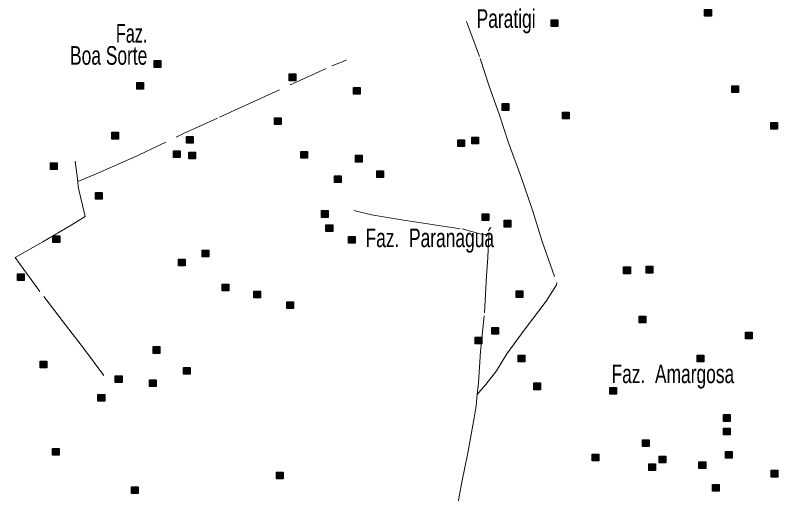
# Model space of a CAD drawing. Extents: x 445.6 to 500, y 8618.1 to 8673.4.
# Drawn here: x 450.11 to 456.69, y 8630.42 to 8634.54 of the extents above; entities that cross this region are included whole.
import ezdxf
from ezdxf.enums import TextEntityAlignment as Align

# ---------------------------------------------------------------- set-up
doc = ezdxf.new("R2010")
doc.units = 0
doc.header["$LTSCALE"] = 0.064
doc.linetypes.add('DOT_DASHED', pattern=[7.7, 5, -1.2, 0.3, -1.2])
doc.layers.add('2', color=7, linetype='Continuous', lineweight=25)
doc.layers.add('22', color=7, linetype='DOT_DASHED', lineweight=13)
doc.layers.add('61', color=7, linetype='Continuous')

msp = doc.modelspace()

# ---------------------------------------------------------------- hatches: boundary and pattern name
at = {"layer": '2'}
for points in [[(456.0553, 8634.5853), (456.1133, 8634.5853), (456.1133, 8634.5273), (456.0553, 8634.5273)], [(454.7328, 8634.4961), (454.7908, 8634.4961), (454.7908, 8634.4381), (454.7328, 8634.4381)], [(451.3121, 8634.1451), (451.3701, 8634.1451), (451.3701, 8634.0871), (451.3121, 8634.0871)], [(452.4755, 8634.0302), (452.5335, 8634.0302), (452.5335, 8633.9722), (452.4755, 8633.9722)], [(451.1624, 8633.9561), (451.2204, 8633.9561), (451.2204, 8633.8981), (451.1624, 8633.8981)], [(453.0297, 8633.9135), (453.0877, 8633.9135), (453.0877, 8633.8555), (453.0297, 8633.8555)], [(456.2893, 8633.9276), (456.3473, 8633.9276), (456.3473, 8633.8696), (456.2893, 8633.8696)], [(454.3098, 8633.7746), (454.3678, 8633.7746), (454.3678, 8633.7166), (454.3098, 8633.7166)], [(452.3481, 8633.6523), (452.4061, 8633.6523), (452.4061, 8633.5943), (452.3481, 8633.5943)], [(454.8307, 8633.7023), (454.8887, 8633.7023), (454.8887, 8633.6443), (454.8307, 8633.6443)], [(456.6261, 8633.6126), (456.6841, 8633.6126), (456.6841, 8633.5546), (456.6261, 8633.5546)], [(450.9463, 8633.5281), (451.0043, 8633.5281), (451.0043, 8633.4701), (450.9463, 8633.4701)], [(451.5889, 8633.4911), (451.6469, 8633.4911), (451.6469, 8633.4331), (451.5889, 8633.4331)], [(453.9274, 8633.4633), (453.9854, 8633.4633), (453.9854, 8633.4053), (453.9274, 8633.4053)], [(454.0493, 8633.4855), (454.1073, 8633.4855), (454.1073, 8633.4275), (454.0493, 8633.4275)], [(451.478, 8633.3688), (451.536, 8633.3688), (451.536, 8633.3108), (451.478, 8633.3108)], [(451.611, 8633.3577), (451.669, 8633.3577), (451.669, 8633.2997), (451.611, 8633.2997)], [(452.5753, 8633.3632), (452.6333, 8633.3632), (452.6333, 8633.3052), (452.5753, 8633.3052)], [(453.0463, 8633.3299), (453.1043, 8633.3299), (453.1043, 8633.2719), (453.0463, 8633.2719)], [(450.4171, 8633.2646), (450.4751, 8633.2646), (450.4751, 8633.2066), (450.4171, 8633.2066)], [(453.2292, 8633.1965), (453.2872, 8633.1965), (453.2872, 8633.1385), (453.2292, 8633.1385)], [(452.8642, 8633.1535), (452.9222, 8633.1535), (452.9222, 8633.0955), (452.8642, 8633.0955)], [(450.805, 8633.009), (450.863, 8633.009), (450.863, 8632.951), (450.805, 8632.951)], [(452.7533, 8632.8534), (452.8113, 8632.8534), (452.8113, 8632.7954), (452.7533, 8632.7954)], [(454.1387, 8632.8256), (454.1967, 8632.8256), (454.1967, 8632.7676), (454.1387, 8632.7676)], [(452.7921, 8632.7311), (452.8501, 8632.7311), (452.8501, 8632.6731), (452.7921, 8632.6731)], [(454.3272, 8632.77), (454.3852, 8632.77), (454.3852, 8632.712), (454.3272, 8632.712)], [(450.4393, 8632.6366), (450.4973, 8632.6366), (450.4973, 8632.5786), (450.4393, 8632.5786)], [(452.9861, 8632.631), (453.0441, 8632.631), (453.0441, 8632.573), (452.9861, 8632.573)], [(451.7249, 8632.5143), (451.7829, 8632.5143), (451.7829, 8632.4563), (451.7249, 8632.4563)], [(451.5199, 8632.4365), (451.5779, 8632.4365), (451.5779, 8632.3785), (451.5199, 8632.3785)], [(455.3572, 8632.3683), (455.4152, 8632.3683), (455.4152, 8632.3103), (455.3572, 8632.3103)], [(455.5511, 8632.3739), (455.6091, 8632.3739), (455.6091, 8632.3159), (455.5511, 8632.3159)], [(450.1345, 8632.3086), (450.1925, 8632.3086), (450.1925, 8632.2506), (450.1345, 8632.2506)], [(451.8967, 8632.2197), (451.9547, 8632.2197), (451.9547, 8632.1617), (451.8967, 8632.1617)], [(452.169, 8632.1594), (452.227, 8632.1594), (452.227, 8632.1014), (452.169, 8632.1014)], [(454.4317, 8632.1627), (454.4897, 8632.1627), (454.4897, 8632.1047), (454.4317, 8632.1047)], [(452.454, 8632.0686), (452.512, 8632.0686), (452.512, 8632.0106), (452.454, 8632.0106)], [(455.4902, 8631.9459), (455.5482, 8631.9459), (455.5482, 8631.8879), (455.4902, 8631.8879)], [(454.2219, 8631.8473), (454.2799, 8631.8473), (454.2799, 8631.7893), (454.2219, 8631.7893)], [(456.4068, 8631.8081), (456.4648, 8631.8081), (456.4648, 8631.7501), (456.4068, 8631.7501)], [(454.0778, 8631.764), (454.1358, 8631.764), (454.1358, 8631.706), (454.0778, 8631.706)], [(451.3023, 8631.6824), (451.3603, 8631.6824), (451.3603, 8631.6244), (451.3023, 8631.6244)], [(454.4491, 8631.6083), (454.5071, 8631.6083), (454.5071, 8631.5503), (454.4491, 8631.5503)], [(455.9912, 8631.608), (456.0492, 8631.608), (456.0492, 8631.55), (455.9912, 8631.55)], [(450.3299, 8631.558), (450.3879, 8631.558), (450.3879, 8631.5), (450.3299, 8631.5)], [(451.5642, 8631.5027), (451.6222, 8631.5027), (451.6222, 8631.4447), (451.5642, 8631.4447)], [(450.9768, 8631.4304), (451.0348, 8631.4304), (451.0348, 8631.3724), (450.9768, 8631.3724)], [(451.2705, 8631.3971), (451.3285, 8631.3971), (451.3285, 8631.3391), (451.2705, 8631.3391)], [(454.5821, 8631.3693), (454.6401, 8631.3693), (454.6401, 8631.3113), (454.5821, 8631.3113)], [(455.2375, 8631.3301), (455.2955, 8631.3301), (455.2955, 8631.2721), (455.2375, 8631.2721)], [(450.8272, 8631.2693), (450.8852, 8631.2693), (450.8852, 8631.2113), (450.8272, 8631.2113)], [(456.2184, 8631.0967), (456.2764, 8631.0967), (456.2764, 8631.0387), (456.2184, 8631.0387)], [(456.2184, 8630.9799), (456.2764, 8630.9799), (456.2764, 8630.9219), (456.2184, 8630.9219)], [(455.5201, 8630.8799), (455.5781, 8630.8799), (455.5781, 8630.8219), (455.5201, 8630.8219)], [(450.4361, 8630.8058), (450.4941, 8630.8058), (450.4941, 8630.7478), (450.4361, 8630.7478)], [(455.087, 8630.7563), (455.145, 8630.7563), (455.145, 8630.6983), (455.087, 8630.6983)], [(456.235, 8630.7798), (456.293, 8630.7798), (456.293, 8630.7218), (456.235, 8630.7218)], [(455.6633, 8630.7397), (455.7213, 8630.7397), (455.7213, 8630.6817), (455.6633, 8630.6817)], [(456.0069, 8630.6896), (456.0649, 8630.6896), (456.0649, 8630.6316), (456.0069, 8630.6316)], [(455.5747, 8630.673), (455.6327, 8630.673), (455.6327, 8630.615), (455.5747, 8630.615)], [(456.6276, 8630.6174), (456.6856, 8630.6174), (456.6856, 8630.5594), (456.6276, 8630.5594)], [(452.3654, 8630.6023), (452.4234, 8630.6023), (452.4234, 8630.5443), (452.3654, 8630.5443)], [(456.1219, 8630.4949), (456.1799, 8630.4949), (456.1799, 8630.4369), (456.1219, 8630.4369)], [(451.1153, 8630.4744), (451.1733, 8630.4744), (451.1733, 8630.4164), (451.1153, 8630.4164)]]:
    msp.add_hatch(color=256, dxfattribs=at).paths.add_polyline_path(points)

# ---------------------------------------------------------------- linework, layer by layer
for points in [[(456.0553, 8634.5853), (456.1133, 8634.5853), (456.1133, 8634.5273), (456.0553, 8634.5273)], [(454.7328, 8634.4961), (454.7908, 8634.4961), (454.7908, 8634.4381), (454.7328, 8634.4381)], [(451.3121, 8634.1451), (451.3701, 8634.1451), (451.3701, 8634.0871), (451.3121, 8634.0871)], [(452.4755, 8634.0302), (452.5335, 8634.0302), (452.5335, 8633.9722), (452.4755, 8633.9722)], [(451.1624, 8633.9561), (451.2204, 8633.9561), (451.2204, 8633.8981), (451.1624, 8633.8981)], [(453.0297, 8633.9135), (453.0877, 8633.9135), (453.0877, 8633.8555), (453.0297, 8633.8555)], [(456.2893, 8633.9276), (456.3473, 8633.9276), (456.3473, 8633.8696), (456.2893, 8633.8696)], [(454.3098, 8633.7746), (454.3678, 8633.7746), (454.3678, 8633.7166), (454.3098, 8633.7166)], [(452.3481, 8633.6523), (452.4061, 8633.6523), (452.4061, 8633.5943), (452.3481, 8633.5943)], [(454.8307, 8633.7023), (454.8887, 8633.7023), (454.8887, 8633.6443), (454.8307, 8633.6443)], [(456.6261, 8633.6126), (456.6841, 8633.6126), (456.6841, 8633.5546), (456.6261, 8633.5546)], [(450.9463, 8633.5281), (451.0043, 8633.5281), (451.0043, 8633.4701), (450.9463, 8633.4701)], [(451.5889, 8633.4911), (451.6469, 8633.4911), (451.6469, 8633.4331), (451.5889, 8633.4331)], [(453.9274, 8633.4633), (453.9854, 8633.4633), (453.9854, 8633.4053), (453.9274, 8633.4053)], [(454.0493, 8633.4855), (454.1073, 8633.4855), (454.1073, 8633.4275), (454.0493, 8633.4275)], [(451.478, 8633.3688), (451.536, 8633.3688), (451.536, 8633.3108), (451.478, 8633.3108)], [(451.611, 8633.3577), (451.669, 8633.3577), (451.669, 8633.2997), (451.611, 8633.2997)], [(452.5753, 8633.3632), (452.6333, 8633.3632), (452.6333, 8633.3052), (452.5753, 8633.3052)], [(453.0463, 8633.3299), (453.1043, 8633.3299), (453.1043, 8633.2719), (453.0463, 8633.2719)], [(450.4171, 8633.2646), (450.4751, 8633.2646), (450.4751, 8633.2066), (450.4171, 8633.2066)], [(453.2292, 8633.1965), (453.2872, 8633.1965), (453.2872, 8633.1385), (453.2292, 8633.1385)], [(452.8642, 8633.1535), (452.9222, 8633.1535), (452.9222, 8633.0955), (452.8642, 8633.0955)], [(450.805, 8633.009), (450.863, 8633.009), (450.863, 8632.951), (450.805, 8632.951)], [(452.7533, 8632.8534), (452.8113, 8632.8534), (452.8113, 8632.7954), (452.7533, 8632.7954)], [(454.1387, 8632.8256), (454.1967, 8632.8256), (454.1967, 8632.7676), (454.1387, 8632.7676)], [(452.7921, 8632.7311), (452.8501, 8632.7311), (452.8501, 8632.6731), (452.7921, 8632.6731)], [(454.3272, 8632.77), (454.3852, 8632.77), (454.3852, 8632.712), (454.3272, 8632.712)], [(450.4393, 8632.6366), (450.4973, 8632.6366), (450.4973, 8632.5786), (450.4393, 8632.5786)], [(452.9861, 8632.631), (453.0441, 8632.631), (453.0441, 8632.573), (452.9861, 8632.573)], [(451.7249, 8632.5143), (451.7829, 8632.5143), (451.7829, 8632.4563), (451.7249, 8632.4563)], [(451.5199, 8632.4365), (451.5779, 8632.4365), (451.5779, 8632.3785), (451.5199, 8632.3785)], [(455.3572, 8632.3683), (455.4152, 8632.3683), (455.4152, 8632.3103), (455.3572, 8632.3103)], [(455.5511, 8632.3739), (455.6091, 8632.3739), (455.6091, 8632.3159), (455.5511, 8632.3159)], [(450.1345, 8632.3086), (450.1925, 8632.3086), (450.1925, 8632.2506), (450.1345, 8632.2506)], [(451.8967, 8632.2197), (451.9547, 8632.2197), (451.9547, 8632.1617), (451.8967, 8632.1617)], [(452.169, 8632.1594), (452.227, 8632.1594), (452.227, 8632.1014), (452.169, 8632.1014)], [(454.4317, 8632.1627), (454.4897, 8632.1627), (454.4897, 8632.1047), (454.4317, 8632.1047)], [(452.454, 8632.0686), (452.512, 8632.0686), (452.512, 8632.0106), (452.454, 8632.0106)], [(455.4902, 8631.9459), (455.5482, 8631.9459), (455.5482, 8631.8879), (455.4902, 8631.8879)], [(454.2219, 8631.8473), (454.2799, 8631.8473), (454.2799, 8631.7893), (454.2219, 8631.7893)], [(456.4068, 8631.8081), (456.4648, 8631.8081), (456.4648, 8631.7501), (456.4068, 8631.7501)], [(454.0778, 8631.764), (454.1358, 8631.764), (454.1358, 8631.706), (454.0778, 8631.706)], [(451.3023, 8631.6824), (451.3603, 8631.6824), (451.3603, 8631.6244), (451.3023, 8631.6244)], [(454.4491, 8631.6083), (454.5071, 8631.6083), (454.5071, 8631.5503), (454.4491, 8631.5503)], [(455.9912, 8631.608), (456.0492, 8631.608), (456.0492, 8631.55), (455.9912, 8631.55)], [(450.3299, 8631.558), (450.3879, 8631.558), (450.3879, 8631.5), (450.3299, 8631.5)], [(451.5642, 8631.5027), (451.6222, 8631.5027), (451.6222, 8631.4447), (451.5642, 8631.4447)], [(450.9768, 8631.4304), (451.0348, 8631.4304), (451.0348, 8631.3724), (450.9768, 8631.3724)], [(451.2705, 8631.3971), (451.3285, 8631.3971), (451.3285, 8631.3391), (451.2705, 8631.3391)], [(454.5821, 8631.3693), (454.6401, 8631.3693), (454.6401, 8631.3113), (454.5821, 8631.3113)], [(455.2375, 8631.3301), (455.2955, 8631.3301), (455.2955, 8631.2721), (455.2375, 8631.2721)], [(450.8272, 8631.2693), (450.8852, 8631.2693), (450.8852, 8631.2113), (450.8272, 8631.2113)], [(456.2184, 8631.0967), (456.2764, 8631.0967), (456.2764, 8631.0387), (456.2184, 8631.0387)], [(456.2184, 8630.9799), (456.2764, 8630.9799), (456.2764, 8630.9219), (456.2184, 8630.9219)], [(455.5201, 8630.8799), (455.5781, 8630.8799), (455.5781, 8630.8219), (455.5201, 8630.8219)], [(450.4361, 8630.8058), (450.4941, 8630.8058), (450.4941, 8630.7478), (450.4361, 8630.7478)], [(455.087, 8630.7563), (455.145, 8630.7563), (455.145, 8630.6983), (455.087, 8630.6983)], [(456.235, 8630.7798), (456.293, 8630.7798), (456.293, 8630.7218), (456.235, 8630.7218)], [(455.6633, 8630.7397), (455.7213, 8630.7397), (455.7213, 8630.6817), (455.6633, 8630.6817)], [(456.0069, 8630.6896), (456.0649, 8630.6896), (456.0649, 8630.6316), (456.0069, 8630.6316)], [(455.5747, 8630.673), (455.6327, 8630.673), (455.6327, 8630.615), (455.5747, 8630.615)], [(456.6276, 8630.6174), (456.6856, 8630.6174), (456.6856, 8630.5594), (456.6276, 8630.5594)], [(452.3654, 8630.6023), (452.4234, 8630.6023), (452.4234, 8630.5443), (452.3654, 8630.5443)], [(456.1219, 8630.4949), (456.1799, 8630.4949), (456.1799, 8630.4369), (456.1219, 8630.4369)], [(451.1153, 8630.4744), (451.1733, 8630.4744), (451.1733, 8630.4164), (451.1153, 8630.4164)]]:
    msp.add_lwpolyline(points, close=True, dxfattribs=at)
at = {"layer": '22'}
for points in [[(454.0038, 8634.4818), (454.1202, 8634.1643), (454.1987, 8633.9255), (454.2875, 8633.6766), (454.3629, 8633.446), (454.4722, 8633.1493), (454.5746, 8632.8492), (454.654, 8632.588), (454.7803, 8632.2333), (454.7798, 8632.2148), (454.691, 8632.075), (454.51, 8631.8363), (454.3496, 8631.6214), (454.2613, 8631.4738), (454.1694, 8631.357), (454.1277, 8631.307), (454.0962, 8631.2705)], [(450.6523, 8633.1037), (450.8274, 8633.1754), (451.1218, 8633.3061), (451.5649, 8633.5172), (451.8757, 8633.6577), (452.1014, 8633.7622), (452.5038, 8633.9452), (452.8424, 8634.1005), (452.9405, 8634.1364), (452.9702, 8634.1527)], [(450.6523, 8633.1037), (450.6377, 8633.2375), (450.6294, 8633.2787)], [(450.8772, 8631.4331), (450.7031, 8631.6702), (450.5559, 8631.8597), (450.3269, 8632.157), (450.1895, 8632.3465), (450.1143, 8632.4511), (450.3531, 8632.584), (450.5951, 8632.7278), (450.7162, 8632.8029), (450.6573, 8633.0578), (450.6523, 8633.1037)], [(453.0312, 8632.8554), (453.1844, 8632.8161), (453.4589, 8632.7709), (453.6338, 8632.7468), (453.9657, 8632.6955), (454.1195, 8632.6534), (454.1949, 8632.6443), (454.1859, 8632.4485), (454.1768, 8632.2918), (454.1565, 8631.9466), (454.1233, 8631.6393), (454.1053, 8631.3694), (454.0962, 8631.2705)], [(454.0962, 8631.2705), (454.0872, 8631.1736), (454.0691, 8631.0681), (454.0144, 8630.7683), (453.9632, 8630.5153), (453.9239, 8630.2983), (453.8483, 8629.9288), (453.8211, 8629.7721), (453.7577, 8629.43), (453.6973, 8629.1377), (453.6521, 8628.8967), (453.5825, 8628.5663), (453.574, 8628.5226)]]:
    msp.add_lwpolyline(points, dxfattribs=at)

# ---------------------------------------------------------------- texts
at = {"layer": '61', "width": 0.7}
for s, p in [('Paratigi', (454.0905, 8634.4274)), ('Faz.  Paranaguá', (453.1333, 8632.5389)), ('Faz.  Amargosa', (455.2531, 8631.3682))]:
    msp.add_text(s, height=0.16, dxfattribs=at).set_placement(p)
at = {"layer": '61'}
for s, width, p in [('Faz.', 0.65, (451.2526, 8634.2999)), ('Boa Sorte', 0.7, (451.2526, 8634.1099))]:
    msp.add_text(s, height=0.16, dxfattribs=dict(at, width=width)).set_placement(p, align=Align.RIGHT)

doc.saveas('drawing.dxf')
